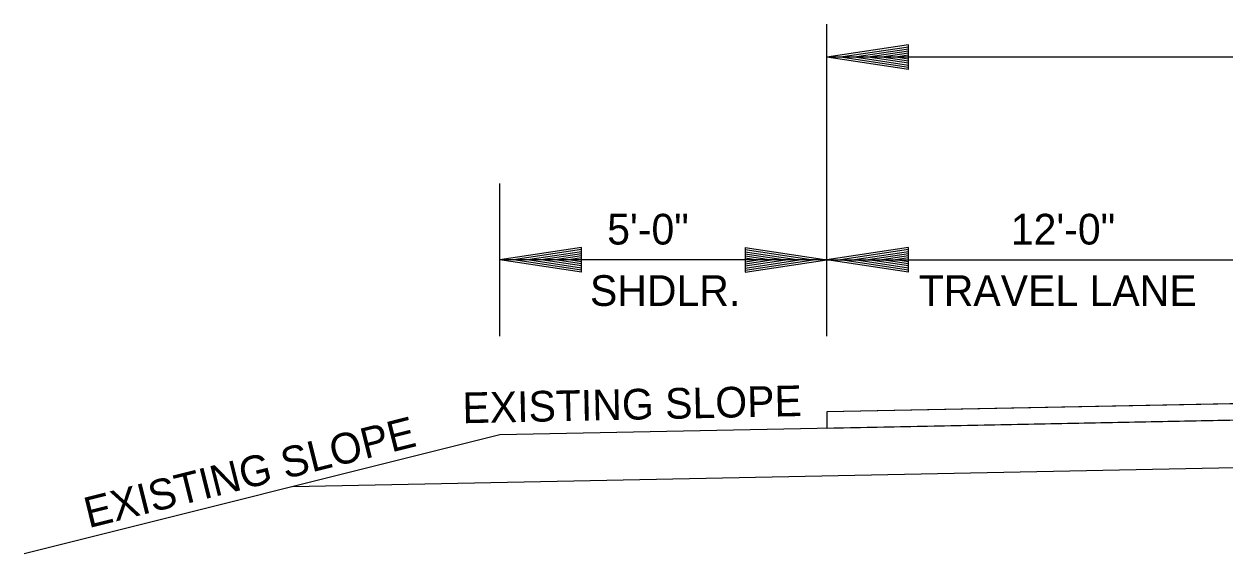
# Model space of a CAD drawing. Extents: x 34757 to 38214, y 51436 to 59430.
# Drawn here: x 36717.4 to 37158.2, y 53689.6 to 53883.9 of the extents above; entities that cross this region are included whole.
import ezdxf

# ---------------------------------------------------------------- set-up
doc = ezdxf.new("R2010")
doc.units = 0
doc.layers.add('Default', color=7, linetype='Continuous')

msp = doc.modelspace()

# ---------------------------------------------------------------- linework, layer by layer
at = {"layer": 'Default'}
for p, q in [((37012.02, 53769.45), (37012.02, 53883.87)), ((37042.02, 53876.2), (37012.02, 53871.7)), ((37042.02, 53875.45), (37017.03, 53871.7)), ((37042.02, 53867.2), (37042.02, 53876.2)), ((37912.02, 53871.72), (37012.02, 53871.7)), ((37042.02, 53867.2), (37012.02, 53871.7)), ((37042.02, 53867.95), (37017.03, 53871.7)), ((37042.02, 53874.69), (37022.19, 53871.7)), ((37042.02, 53868.72), (37022.19, 53871.7)), ((37042.02, 53873.94), (37027.18, 53871.7)), ((37042.02, 53869.47), (37027.18, 53871.7)), ((37042.02, 53873.17), (37032.27, 53871.7)), ((37042.02, 53870.25), (37032.27, 53871.7)), ((37042.02, 53872.41), (37037.28, 53871.7)), ((37042.02, 53871), (37037.28, 53871.7)), ((36892.02, 53769.45), (36892.02, 53825.43)), ((37012.02, 53769.45), (37012.02, 53825.43)), ((36922.02, 53801.94), (36892.02, 53797.44)), ((36922.02, 53801.19), (36897.03, 53797.44)), ((36922.02, 53800.42), (36902.19, 53797.44)), ((36922.02, 53792.94), (36922.02, 53801.94)), ((36982.02, 53801.94), (37012.02, 53797.44)), ((36982.02, 53801.94), (36982.02, 53792.94)), ((36982.02, 53801.19), (37007.01, 53797.44)), ((36982.02, 53800.42), (37001.85, 53797.44)), ((37042.02, 53801.94), (37012.02, 53797.44)), ((37042.02, 53801.19), (37017.03, 53797.44)), ((37042.02, 53800.42), (37022.19, 53797.44)), ((37042.02, 53792.94), (37042.02, 53801.94)), ((37012.02, 53797.44), (36892.02, 53797.44)), ((36922.02, 53792.94), (36892.02, 53797.44)), ((36922.02, 53793.69), (36897.03, 53797.44)), ((36922.02, 53794.45), (36902.19, 53797.44)), ((36922.02, 53799.67), (36907.18, 53797.44)), ((36922.02, 53795.2), (36907.18, 53797.44)), ((36922.02, 53798.91), (36912.27, 53797.44)), ((36922.02, 53795.98), (36912.27, 53797.44)), ((36922.02, 53798.14), (36917.28, 53797.44)), ((36922.02, 53796.73), (36917.28, 53797.44)), ((36982.02, 53799.67), (36996.85, 53797.44)), ((36982.02, 53798.89), (36991.77, 53797.44)), ((36982.02, 53798.14), (36986.76, 53797.44)), ((36982.02, 53792.94), (37012.02, 53797.44)), ((36982.02, 53795.97), (36991.77, 53797.44)), ((36982.02, 53794.45), (37001.85, 53797.44)), ((36982.02, 53793.69), (37007.01, 53797.44)), ((36982.02, 53795.2), (36996.85, 53797.44)), ((36982.02, 53796.73), (36986.76, 53797.44)), ((37012.02, 53797.44), (37192.02, 53797.44)), ((37042.02, 53792.94), (37012.02, 53797.44)), ((37042.02, 53793.69), (37017.03, 53797.44)), ((37042.02, 53794.45), (37022.19, 53797.44)), ((37042.02, 53799.67), (37027.18, 53797.44)), ((37042.02, 53795.2), (37027.18, 53797.44)), ((37042.02, 53798.91), (37032.27, 53797.44)), ((37042.02, 53795.98), (37032.27, 53797.44)), ((37042.02, 53798.14), (37037.28, 53797.44)), ((37042.02, 53796.73), (37037.28, 53797.44)), ((37462.02, 53750.71), (37012.02, 53741.7)), ((37012.02, 53741.7), (37012.02, 53735.7)), ((36892.02, 53733.3), (36717.39, 53689.65)), ((37462.02, 53727.2), (36815.91, 53714.28))]:
    msp.add_line(p, q, dxfattribs=at)
msp.add_lwpolyline([(37012.02, 53741.7), (37012.02, 53735.7), (37462.02, 53744.7), (37912.02, 53735.7), (37912.02, 53741.7), (37462.02, 53750.71)], close=True, dxfattribs=at)
msp.add_lwpolyline([(37462.02, 53744.7), (36892.02, 53733.3)], dxfattribs=at)

# ---------------------------------------------------------------- texts
for s, p in [('5\'-0"', (36931.42, 53803.06)), ('12\'-0"', (37079.56, 53803.06)), ('SHDLR.', (36925.09, 53780.56)), ('TRAVEL LANE', (37045.77, 53780.56))]:
    msp.add_text(s, height=11.25, dxfattribs=at).set_placement(p)
for rotation, p in [(1.2244, (36878.42, 53737.54)), (14.0368, (36741.11, 53699.05))]:
    msp.add_text('EXISTING SLOPE', height=11.25, rotation=rotation, dxfattribs=at).set_placement(p)

doc.saveas('drawing.dxf')
